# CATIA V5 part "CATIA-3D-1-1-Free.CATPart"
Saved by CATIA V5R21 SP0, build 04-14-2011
Part number: CATIA-3D-1-1-Free
Bounding box of the stored display mesh (mm): x -89 to 89, y -32 to 32, z 0 to 64
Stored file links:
  C:\Users\Rasoul Mohammadi\Desktop\CATIA-Free\3D\CATIA-3D-1-1-Free.CATPart
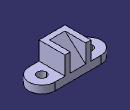
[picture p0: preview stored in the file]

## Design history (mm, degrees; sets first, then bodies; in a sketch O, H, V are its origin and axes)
Body1 (main body)
  Sketch1 on xy-plane, origin (0, 0, 0), H (1, 0, 0), V (0, 1, 0)
    construction line L1 (57, 0) -> (-57, 0)
    point P1 (57, 0)
    point P2 (-57, 0)
    line L2 (57, -32) -> (-57, -32)
    line L3 (-57, 32) -> (57, 32)
    arc A1 centre (-57, 0) radius 32 from (-57, -32) to (-57, 32) cw
    arc A2 centre (57, 0) radius 32 from (57, 32) to (57, -32) cw
    circle A3 centre (57, 0) radius 11
    circle A4 centre (-57, 0) radius 11
    distance L1 L2 = 32
    length L1 = 114
    radius A3 = 11
    coincidence: P1 H
    horizontal: L1 H
    tangency: A1 L2, A2 L2, A1 L3, A2 L3
    symmetry: P1 P2 V, A3 A4 V
  Pad1: profile Sketch1, direction (0, 0, 1), length 19
  Sketch2 on end face of Pad1, origin (0, 0, 19), H (1, 0, 0), V (0, 1, 0)
    line L1 (32, 32) -> (32, -32)
    line L2 (32, -32) -> (-32, -32)
    line L3 (-32, -32) -> (-32, 32)
    line L4 (-32, 32) -> (32, 32)
    reference projected line E1 (57, 32) -> (-57, 32) from edge [face of Pad1 from Sketch1.L3 | end face of Pad1]
    length L4 = 64
    vertical: L1 V, L3 V
    horizontal: L2 H, L4 H
    equidistance: L1 L3 O, L2 L4 O
    coincidence: L4 E1
  Pad2: profile Sketch2, direction (0, 0, 1), length 45
  Sketch3 on yz-plane, origin (0, 0, 0), H (0, 1, 0), V (0, 0, 1)
    projected line E1 (-32, 64) -> (32, 64) from edge [face of Pad2 from Sketch2.L1 | end face of Pad2]
    projected line E2 (-19, 64) -> (32, 64) from edge [face of Pad2 from Sketch2.L1 | end face of Pad2]
    point P2 (32, 64)
    projected line E3 (32, 19) -> (32, 64) from edge [face of Pad2 | face of Pad2 from Sketch2.L1]
    point P4 (32, 64)
    line L1 (32, 19) -> (-19, 64)
    point P5 (-19, 64)
    reference projected line E4 (-32, 19) -> (-32, 64) from edge [face of Pad2 from Sketch2.L1 | face of Pad2]
    distance P5 E4 = 13
    coincidence: P2 P4
  Pocket1: profile Sketch3, direction (-1, 0, 0), length 19, mirrored extent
